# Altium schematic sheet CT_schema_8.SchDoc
size 274 x 160 mm
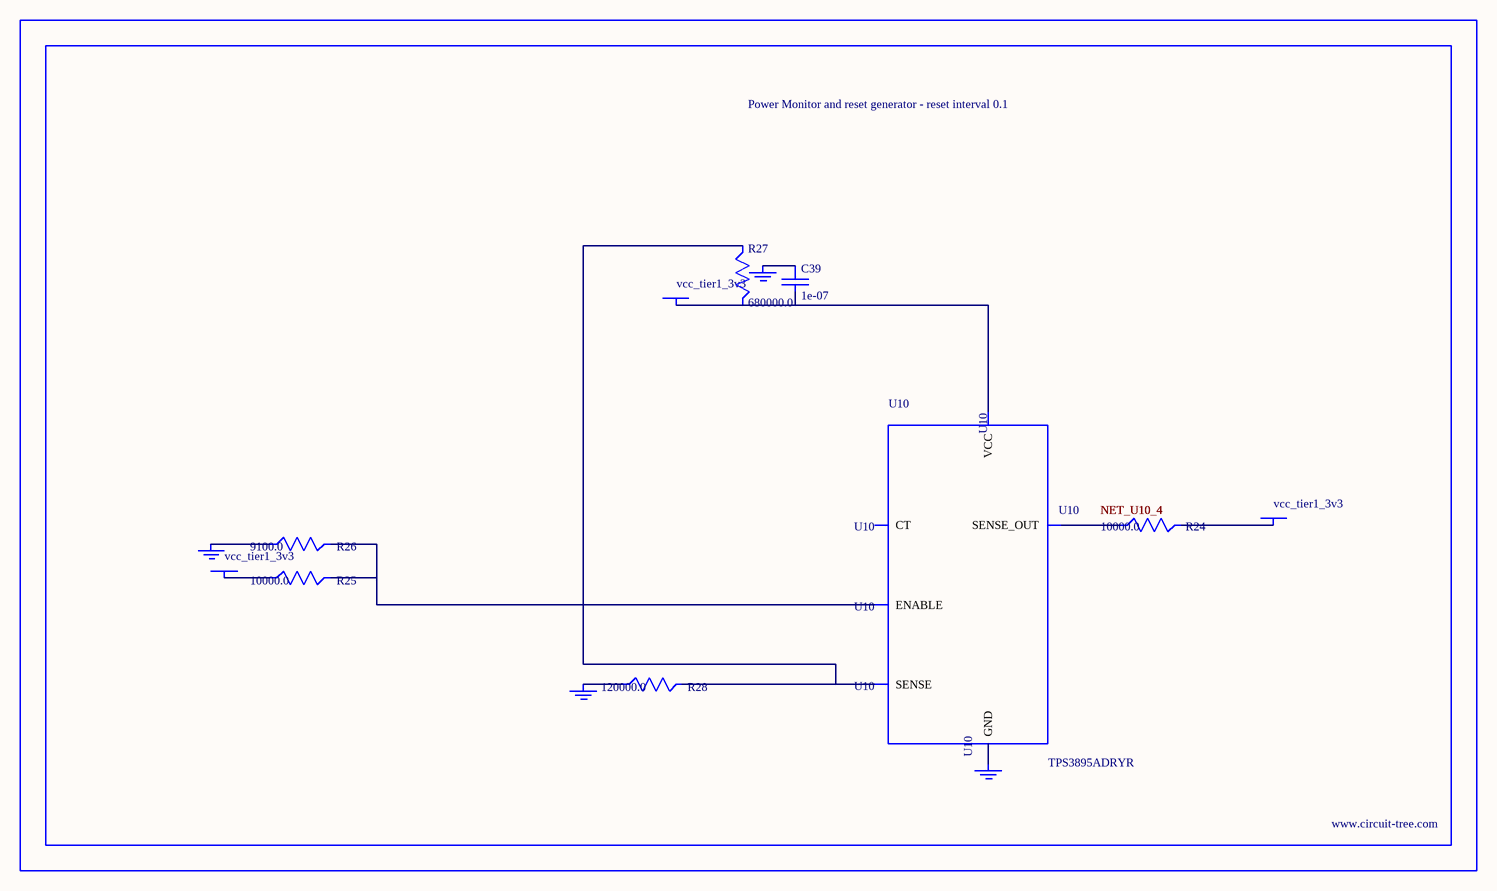
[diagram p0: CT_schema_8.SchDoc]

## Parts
BORDER7  (no value)
C39  1e-07  [C0402]
GND_INSTANCE_7_0  (no value)
GND_INSTANCE_7_1  (no value)
GND_INSTANCE_7_2  (no value)
GND_INSTANCE_7_3  (no value)
POWER_INSTANCE_7_0  vcc_tier1_3v3
POWER_INSTANCE_7_1  vcc_tier1_3v3
POWER_INSTANCE_7_2  vcc_tier1_3v3
R24  10000.0  [R0603]
R25  10000.0  [R0603]
R26  9100.0  [R0603]
R27  680000.0  [R0603]
R28  120000.0  [R0603]
U10  TPS3895ADRYR  [SON-6]

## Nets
NetC39_1: C39.1 GND_INSTANCE_7_2.0(GND)
NetC39_2: C39.2 POWER_INSTANCE_7_2.0(PWR) R27.2 U10.6(VCC)
NetGND_INSTANCE_7_0_0: GND_INSTANCE_7_0.0(GND) R26.1
NetGND_INSTANCE_7_1_0: GND_INSTANCE_7_1.0(GND) R28.1
NetGND_INSTANCE_7_3_0: GND_INSTANCE_7_3.0(GND) U10.2(GND)
NetPOWER_INSTANCE_7_0_0: POWER_INSTANCE_7_0.0(PWR) R25.1
NetPOWER_INSTANCE_7_1_0: POWER_INSTANCE_7_1.0(PWR) R24.2
NetR24_1: R24.1 U10.4(SENSE_OUT)
NetR25_2: R25.2 R26.2 U10.1(ENABLE)
NetR27_1: R27.1 R28.2 U10.3(SENSE)

Not connected (* = marked no-connect by the designer): U10 5(CT)

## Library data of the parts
BORDER7 = BORDER_PAGE7
C39 = C0402C104K3RACTU
GND_INSTANCE_7_0-GND_INSTANCE_7_3 = GND
POWER_INSTANCE_7_0-POWER_INSTANCE_7_2 = PWR
R24 R25 = RC0603JR-0710KL
R26 = RC0603JR-079K1L
R27 = RC0603JR-07680KL
R28 = RC0603JR-07120KL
